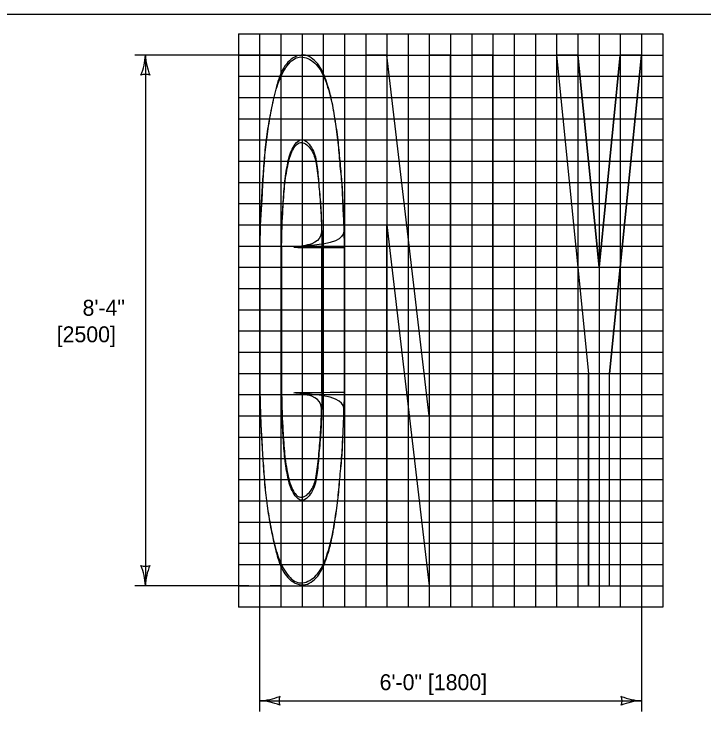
# Model space of a CAD drawing. Extents: x 49991.4 to 50021, y 49987.6 to 50011.4.
# Drawn here: x 50003.057 to 50005.656, y 50008.552 to 50011.263 of the extents above; entities that cross this region are included whole.
import ezdxf

# ---------------------------------------------------------------- set-up
doc = ezdxf.new("R2010")
doc.units = 0
for name, color, linetype in [('Level 1', 7, 'Continuous'), ('Level 2', 7, 'Continuous'), ('Level 3', 7, 'Continuous'), ('Level 9', 7, 'Continuous')]:
    doc.layers.add(name, color=color, linetype=linetype)

msp = doc.modelspace()

# ---------------------------------------------------------------- linework, layer by layer
at = {"layer": 'Level 1'}
for p, q in [((50004.462, 50011.1097), (50004.382, 50011.1097)), ((50004.382, 50011.1097), (50004.382, 50009.1096)), ((50004.462, 50011.1097), (50004.382, 50011.1097)), ((50004.382, 50011.1097), (50004.382, 50009.1096)), ((50004.462, 50011.1097), (50004.382, 50011.1097)), ((50004.382, 50011.1097), (50004.382, 50009.1096)), ((50004.462, 50011.1097), (50004.382, 50011.1097)), ((50004.382, 50011.1097), (50004.382, 50009.1096)), ((50004.622, 50009.7496), (50004.462, 50011.1097)), ((50004.622, 50009.7496), (50004.462, 50011.1097)), ((50004.622, 50009.7496), (50004.462, 50011.1097)), ((50004.622, 50009.7496), (50004.462, 50011.1097)), ((50004.702, 50011.1097), (50004.622, 50011.1097)), ((50004.622, 50011.1097), (50004.622, 50009.7496)), ((50004.702, 50011.1097), (50004.622, 50011.1097)), ((50004.622, 50011.1097), (50004.622, 50009.7496)), ((50004.702, 50011.1097), (50004.622, 50011.1097)), ((50004.622, 50011.1097), (50004.622, 50009.7496)), ((50004.702, 50011.1097), (50004.622, 50011.1097)), ((50004.622, 50011.1097), (50004.622, 50009.7496)), ((50004.702, 50009.1096), (50004.702, 50011.1097)), ((50004.702, 50009.1096), (50004.702, 50011.1097)), ((50004.702, 50009.1096), (50004.702, 50011.1097)), ((50004.702, 50009.1096), (50004.702, 50011.1097)), ((50004.862, 50011.1097), (50004.782, 50011.1097)), ((50004.782, 50011.1097), (50004.782, 50009.1096)), ((50004.862, 50011.1097), (50004.782, 50011.1097)), ((50004.782, 50011.1097), (50004.782, 50009.1096)), ((50004.862, 50011.1097), (50004.782, 50011.1097)), ((50004.782, 50011.1097), (50004.782, 50009.1096)), ((50004.862, 50011.1097), (50004.782, 50011.1097)), ((50004.782, 50011.1097), (50004.782, 50009.1096)), ((50004.862, 50009.4296), (50004.862, 50011.1097)), ((50004.862, 50009.4296), (50004.862, 50011.1097)), ((50004.862, 50009.4296), (50004.862, 50011.1097)), ((50004.862, 50009.4296), (50004.862, 50011.1097)), ((50005.102, 50011.1097), (50005.182, 50011.1097)), ((50005.102, 50011.1097), (50005.222, 50009.9096)), ((50005.182, 50011.1097), (50005.102, 50011.1097)), ((50005.102, 50011.1097), (50005.222, 50009.9096)), ((50005.182, 50011.1097), (50005.102, 50011.1097)), ((50005.102, 50011.1097), (50005.222, 50009.9096)), ((50005.182, 50011.1097), (50005.102, 50011.1097)), ((50005.102, 50011.1097), (50005.222, 50009.9096)), ((50005.182, 50011.1097), (50005.262, 50010.3096)), ((50005.262, 50010.3096), (50005.182, 50011.1097)), ((50005.262, 50010.3096), (50005.182, 50011.1097)), ((50005.262, 50010.3096), (50005.182, 50011.1097)), ((50005.262, 50010.3096), (50005.342, 50011.1097)), ((50005.342, 50011.1097), (50005.262, 50010.3096)), ((50005.342, 50011.1097), (50005.262, 50010.3096)), ((50005.342, 50011.1097), (50005.262, 50010.3096)), ((50005.422, 50011.1097), (50005.302, 50009.9096)), ((50005.302, 50009.9096), (50005.422, 50011.1097)), ((50005.302, 50009.9096), (50005.422, 50011.1097)), ((50005.302, 50009.9096), (50005.422, 50011.1097)), ((50005.342, 50011.1097), (50005.422, 50011.1097)), ((50005.422, 50011.1097), (50005.342, 50011.1097)), ((50005.422, 50011.1097), (50005.342, 50011.1097)), ((50005.422, 50011.1097), (50005.342, 50011.1097)), ((50004.462, 50009.1096), (50004.462, 50010.4696)), ((50004.462, 50010.4696), (50004.622, 50009.1096)), ((50004.462, 50009.1096), (50004.462, 50010.4696)), ((50004.462, 50010.4696), (50004.622, 50009.1096)), ((50004.462, 50009.1096), (50004.462, 50010.4696)), ((50004.462, 50010.4696), (50004.622, 50009.1096)), ((50004.462, 50009.1096), (50004.462, 50010.4696)), ((50004.462, 50010.4696), (50004.622, 50009.1096)), ((50003.9835, 50010.3845), (50003.9835, 50009.8379)), ((50004.0645, 50010.386), (50004.0645, 50009.8365)), ((50004.2165, 50009.838), (50004.2165, 50010.3844)), ((50004.3019, 50010.3838), (50004.3019, 50009.8387)), ((50005.222, 50009.1096), (50005.222, 50009.9096)), ((50005.222, 50009.9096), (50005.222, 50009.1096)), ((50005.222, 50009.9096), (50005.222, 50009.1096)), ((50005.222, 50009.9096), (50005.222, 50009.1096)), ((50005.302, 50009.1096), (50005.302, 50009.9096)), ((50005.302, 50009.1096), (50005.302, 50009.9096)), ((50005.302, 50009.1096), (50005.302, 50009.9096)), ((50005.302, 50009.1096), (50005.302, 50009.9096)), ((50005.102, 50009.4296), (50004.862, 50009.4296)), ((50005.102, 50009.4296), (50004.862, 50009.4296)), ((50005.102, 50009.4296), (50004.862, 50009.4296)), ((50005.102, 50009.4296), (50004.862, 50009.4296)), ((50005.102, 50009.1096), (50005.102, 50009.4296)), ((50005.102, 50009.1096), (50005.102, 50009.4296)), ((50005.102, 50009.1096), (50005.102, 50009.4296)), ((50005.102, 50009.1096), (50005.102, 50009.4296)), ((50004.382, 50009.1096), (50004.462, 50009.1096)), ((50004.382, 50009.1096), (50004.462, 50009.1096)), ((50004.382, 50009.1096), (50004.462, 50009.1096)), ((50004.382, 50009.1096), (50004.462, 50009.1096)), ((50004.622, 50009.1096), (50004.702, 50009.1096)), ((50004.622, 50009.1096), (50004.702, 50009.1096)), ((50004.622, 50009.1096), (50004.702, 50009.1096)), ((50004.622, 50009.1096), (50004.702, 50009.1096)), ((50004.782, 50009.1096), (50005.102, 50009.1096)), ((50004.782, 50009.1096), (50005.102, 50009.1096)), ((50004.782, 50009.1096), (50005.102, 50009.1096)), ((50004.782, 50009.1096), (50005.102, 50009.1096)), ((50005.222, 50009.1096), (50005.302, 50009.1096)), ((50005.222, 50009.1096), (50005.302, 50009.1096)), ((50005.222, 50009.1096), (50005.302, 50009.1096)), ((50005.222, 50009.1096), (50005.302, 50009.1096))]:
    msp.add_line(p, q, dxfattribs=at)
msp.add_lwpolyline([(50008.6146, 50011.2628), (50000.3356, 50011.2628), (50000.3356, 50000.0624), (50008.6146, 50000.0624)], close=True, dxfattribs=at)
for points in [[(50003.9835, 50010.3845), (50003.9835, 50009.8379)], [(50004.0645, 50009.8365), (50004.0645, 50010.386)], [(50004.2165, 50010.3844), (50004.2165, 50009.838)], [(50004.3019, 50009.8387), (50004.3019, 50010.3838)]]:
    msp.add_lwpolyline(points, dxfattribs=at)
for points in [[(50004.3019, 50010.3838), (50004.3017, 50010.4104), (50004.3012, 50010.4626), (50004.296, 50010.5418), (50004.2942, 50010.6213), (50004.2844, 50010.7011), (50004.2795, 50010.7805), (50004.2675, 50010.8602), (50004.2552, 50010.9406), (50004.2334, 50011.0148), (50004.2063, 50011.0802), (50004.1481, 50011.1229), (50004.0829, 50011.0874), (50004.0522, 50011.021), (50004.0331, 50010.9414), (50004.0172, 50010.8616), (50004.0056, 50010.782), (50003.9982, 50010.7018), (50003.9934, 50010.6219), (50003.989, 50010.5416), (50003.9833, 50010.4632), (50003.9834, 50010.4104), (50003.9835, 50010.3845)], [(50003.9835, 50010.3845), (50003.9843, 50010.4621), (50003.9888, 50010.5426), (50003.9934, 50010.6201), (50003.9987, 50010.703), (50004.0063, 50010.782), (50004.0177, 50010.8603), (50004.0337, 50010.9416), (50004.0549, 50011.0206), (50004.0967, 50011.0905), (50004.1423, 50011.1111), (50004.2001, 50011.0776), (50004.2305, 50011.0191), (50004.2533, 50010.9408), (50004.2677, 50010.8588), (50004.2784, 50010.7805), (50004.2852, 50010.7014), (50004.2928, 50010.6217), (50004.2966, 50010.5403), (50004.3004, 50010.4636), (50004.3019, 50010.3838), (50003.9835, 50010.3845), (50004.3019, 50010.3838)], [(50004.0645, 50010.386), (50004.0651, 50010.4131), (50004.0663, 50010.4663), (50004.0704, 50010.5462), (50004.0755, 50010.6254), (50004.0865, 50010.6989), (50004.1, 50010.7547), (50004.1411, 50010.8086), (50004.1871, 50010.7547), (50004.1994, 50010.6968), (50004.2048, 50010.624), (50004.2124, 50010.545), (50004.2164, 50010.4648), (50004.2164, 50010.4118), (50004.2165, 50010.3844)], [(50004.0645, 50010.386), (50004.0668, 50010.4673), (50004.0706, 50010.5456), (50004.0766, 50010.6253), (50004.0888, 50010.7051), (50004.107, 50010.7599), (50004.1389, 50010.791), (50004.1815, 50010.7545), (50004.1967, 50010.7051), (50004.2051, 50010.6246), (50004.2119, 50010.5433), (50004.2157, 50010.4665), (50004.2165, 50010.3844), (50004.0645, 50010.386), (50004.2165, 50010.3844)], [(50003.9835, 50009.8379), (50003.9834, 50009.8121), (50003.9833, 50009.7593), (50003.989, 50009.6809), (50003.9934, 50009.6006), (50003.9982, 50009.5207), (50004.0056, 50009.4405), (50004.0172, 50009.3609), (50004.0331, 50009.281), (50004.0522, 50009.2015), (50004.0829, 50009.135), (50004.1481, 50009.0996), (50004.2063, 50009.1423), (50004.2334, 50009.2076), (50004.2552, 50009.2819), (50004.2675, 50009.3623), (50004.2795, 50009.442), (50004.2844, 50009.5214), (50004.2942, 50009.6011), (50004.296, 50009.6806), (50004.3012, 50009.7598), (50004.3017, 50009.8121), (50004.3019, 50009.8387)], [(50003.9835, 50009.8379), (50003.9843, 50009.7604), (50003.9888, 50009.6798), (50003.9934, 50009.6023), (50003.9987, 50009.5195), (50004.0063, 50009.4405), (50004.0177, 50009.3622), (50004.0337, 50009.2809), (50004.0549, 50009.2018), (50004.0967, 50009.1319), (50004.1423, 50009.1114), (50004.2001, 50009.1448), (50004.2305, 50009.2034), (50004.2533, 50009.2816), (50004.2677, 50009.3637), (50004.2784, 50009.442), (50004.2852, 50009.521), (50004.2928, 50009.6008), (50004.2966, 50009.6821), (50004.3004, 50009.7589), (50004.3019, 50009.8387), (50003.9835, 50009.8379), (50004.3019, 50009.8387)], [(50004.0645, 50009.8365), (50004.0668, 50009.7552), (50004.0706, 50009.6769), (50004.0766, 50009.5971), (50004.0888, 50009.5173), (50004.107, 50009.4626), (50004.1389, 50009.4315), (50004.1815, 50009.4679), (50004.1967, 50009.5173), (50004.2051, 50009.5979), (50004.2119, 50009.6792), (50004.2157, 50009.7559), (50004.2165, 50009.838), (50004.0645, 50009.8365), (50004.2165, 50009.838)], [(50004.2165, 50009.838), (50004.2164, 50009.8107), (50004.2164, 50009.7577), (50004.2124, 50009.6775), (50004.2048, 50009.5985), (50004.1994, 50009.5256), (50004.1871, 50009.4678), (50004.1411, 50009.4138), (50004.1, 50009.4677), (50004.0865, 50009.5236), (50004.0755, 50009.5971), (50004.0704, 50009.6763), (50004.0663, 50009.7562), (50004.0651, 50009.8094), (50004.0645, 50009.8365)]]:
    msp.add_open_spline(points, degree=3, dxfattribs=at)
at = {"layer": 'Level 3'}
for p, q in [((50004.0623, 50011.1097), (50003.5113, 50011.1097)), ((50003.5513, 50011.1097), (50003.5513, 50009.1096)), ((50005.422, 50010.9497), (50005.422, 50008.636)), ((50003.982, 50009.4292), (50003.982, 50008.636)), ((50003.942, 50009.1096), (50003.5113, 50009.1096)), ((50004.062, 50009.1096), (50004.022, 50009.1096)), ((50003.9823, 50008.676), (50005.422, 50008.676))]:
    msp.add_line(p, q, dxfattribs=at)
for centre, radius, start, end in [((50003.3291, 50011.1188), 0.2223, 337.456, 357.6395), ((50003.784, 50011.1212), 0.233, 182.8273, 202.0772), ((50003.5513, 50010.9815), 0.0548, 72.1388, 107.8612), ((50003.5513, 50009.2379), 0.0548, 252.1388, 287.8612), ((50003.3186, 50009.0982), 0.233, 2.8273, 22.0772), ((50003.7734, 50009.1005), 0.2223, 157.456, 177.6395), ((50003.9728, 50008.8981), 0.2223, 272.3605, 292.544), ((50003.9705, 50008.4433), 0.233, 67.9228, 87.1727), ((50004.1102, 50008.676), 0.0548, 162.1388, 197.8612), ((50005.4312, 50008.8981), 0.2223, 247.456, 267.6395), ((50005.2938, 50008.676), 0.0548, 342.1388, 17.8612), ((50005.4335, 50008.4433), 0.233, 92.8273, 112.0772)]:
    msp.add_arc(centre, radius, start, end, dxfattribs=at)
at = {"layer": 'Level 9'}
for p, q in [((50003.902, 50011.1897), (50005.502, 50011.1897)), ((50003.902, 50011.1897), (50003.902, 50009.0289)), ((50003.982, 50011.1897), (50003.982, 50009.0296)), ((50004.062, 50011.1897), (50004.062, 50009.0289)), ((50004.142, 50011.1897), (50004.142, 50009.0289)), ((50004.222, 50011.1897), (50004.222, 50009.0289)), ((50004.302, 50011.1897), (50004.302, 50009.0289)), ((50004.382, 50011.1897), (50004.382, 50009.0289)), ((50004.462, 50011.1897), (50004.462, 50009.0289)), ((50004.542, 50011.1897), (50004.542, 50009.0289)), ((50004.622, 50011.1897), (50004.622, 50009.0289)), ((50004.702, 50011.1897), (50004.702, 50009.0289)), ((50004.782, 50011.1897), (50004.782, 50009.0289)), ((50004.862, 50011.1897), (50004.862, 50009.0289)), ((50004.942, 50011.1897), (50004.942, 50009.0289)), ((50005.022, 50011.1897), (50005.022, 50009.0289)), ((50005.102, 50011.1897), (50005.102, 50009.0289)), ((50005.182, 50011.1897), (50005.182, 50009.0289)), ((50005.262, 50011.1897), (50005.262, 50009.0289)), ((50005.342, 50011.1897), (50005.342, 50009.0289)), ((50005.422, 50011.1897), (50005.422, 50009.0289)), ((50005.502, 50011.1897), (50005.502, 50009.0289)), ((50003.902, 50011.1097), (50005.502, 50011.1097)), ((50004.7152, 50011.1096), (50004.7152, 50011.1096)), ((50003.902, 50011.0297), (50005.502, 50011.0297)), ((50003.902, 50010.9497), (50005.502, 50010.9497)), ((50003.902, 50010.8697), (50005.502, 50010.8697)), ((50003.9783, 50010.8696), (50005.3526, 50010.8696)), ((50003.902, 50010.7897), (50005.502, 50010.7897)), ((50003.9783, 50010.7895), (50005.3526, 50010.7895)), ((50003.902, 50010.7097), (50005.502, 50010.7097)), ((50003.902, 50010.6297), (50005.502, 50010.6297)), ((50003.902, 50010.5497), (50005.502, 50010.5497)), ((50003.902, 50010.4697), (50005.502, 50010.4697)), ((50003.902, 50010.3897), (50005.502, 50010.3897)), ((50003.902, 50010.3097), (50005.502, 50010.3097)), ((50003.902, 50010.2297), (50005.502, 50010.2297)), ((50003.902, 50010.1497), (50005.502, 50010.1497)), ((50003.902, 50010.0697), (50005.502, 50010.0697)), ((50003.902, 50009.9897), (50005.502, 50009.9897)), ((50003.902, 50009.9097), (50005.502, 50009.9097)), ((50003.902, 50009.8297), (50005.502, 50009.8297)), ((50003.902, 50009.7497), (50005.502, 50009.7497)), ((50003.902, 50009.6697), (50005.502, 50009.6697)), ((50003.902, 50009.5897), (50005.502, 50009.5897)), ((50003.902, 50009.5097), (50005.502, 50009.5097)), ((50003.902, 50009.4297), (50005.502, 50009.4297)), ((50003.902, 50009.3496), (50005.502, 50009.3496)), ((50003.902, 50009.2696), (50005.502, 50009.2696)), ((50003.902, 50009.1896), (50005.502, 50009.1896)), ((50003.902, 50009.1096), (50005.502, 50009.1096)), ((50003.902, 50009.0296), (50005.502, 50009.0296))]:
    msp.add_line(p, q, dxfattribs=at)

# ---------------------------------------------------------------- texts
at = {"layer": 'Level 2'}
for s, p in [('8\'-4"', (50003.3144, 50010.1271)), ('[2500]', (50003.217, 50010.0271)), ('6\'-0" [1800]', (50004.4347, 50008.716))]:
    msp.add_text(s, height=0.06, dxfattribs=at).set_placement(p)

doc.saveas('drawing.dxf')
